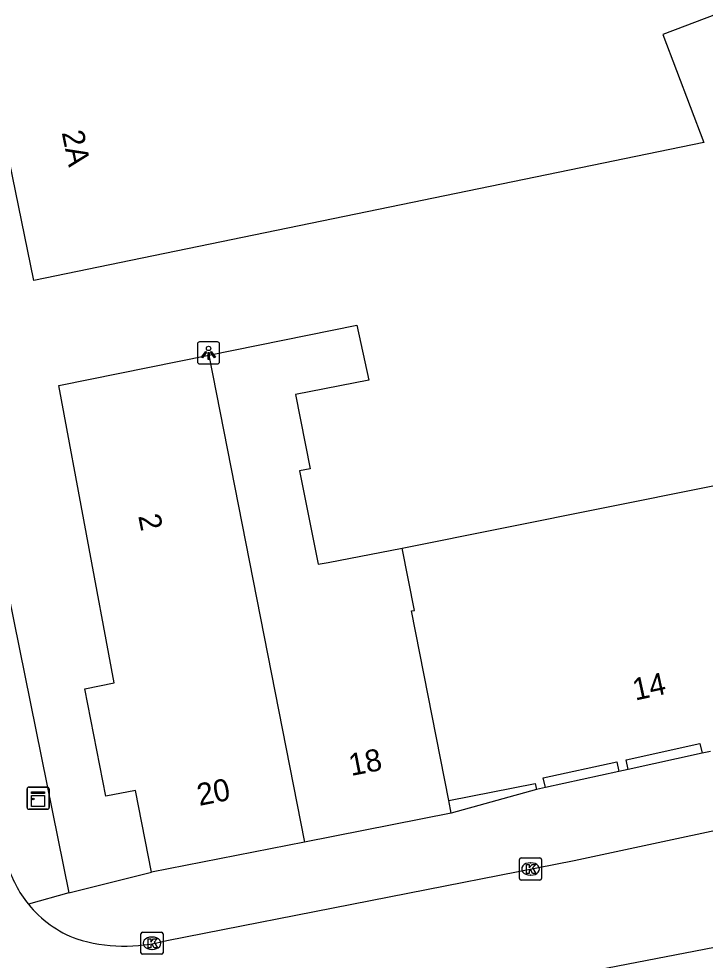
# Model space of a CAD drawing. Extents: x 160026 to 161302, y 384757 to 385701.
# Drawn here: x 160735.46 to 160766.52, y 384838.71 to 384881.28 of the extents above; entities that cross this region are included whole.
import ezdxf

# ---------------------------------------------------------------- set-up
doc = ezdxf.new("R2010")
doc.units = 0
for name, color, linetype in [('IMGEO_Kast', 7, 'Continuous'), ('IMGEO_Kolk', 7, 'Continuous'), ('IMGEO_Lichtpunt', 7, 'Continuous'), ('IMGEO_Pand', 7, 'Continuous'), ('IMGEO_Pand_nummerreeks', 7, 'Continuous'), ('IMGEO_Rijbaan_lokaal_open', 7, 'Continuous'), ('IMGEO_Voetpad_open', 7, 'Continuous')]:
    doc.layers.add(name, color=color, linetype=linetype)

msp = doc.modelspace()

# ---------------------------------------------------------------- linework, layer by layer
at = {"layer": 'IMGEO_Kast'}
for p, q in [((160735.835, 384845.616), (160735.835, 384846.457)), ((160735.835, 384846.457), (160735.835, 384845.616)), ((160735.91, 384846.541), (160736.751, 384846.541)), ((160736.751, 384846.541), (160735.91, 384846.541)), ((160736.835, 384846.466), (160736.835, 384845.625)), ((160736.835, 384845.625), (160736.835, 384846.466)), ((160736.76, 384845.541), (160735.919, 384845.541)), ((160735.919, 384845.541), (160736.76, 384845.541))]:
    msp.add_line(p, q, dxfattribs=at)
for points in [[(160736.03, 384846.331), (160736.63, 384846.331), (160736.63, 384846.246), (160736.03, 384846.246), (160736.03, 384846.331)], [(160736.03, 384846.156), (160736.63, 384846.156), (160736.63, 384845.667), (160736.03, 384845.667), (160736.03, 384846.156)]]:
    msp.add_lwpolyline(points, dxfattribs=at)
msp.add_circle((160736.114, 384846.005), 0.0377, dxfattribs=at)
for centre, start, end in [((160735.913, 384846.463), 92.4484, 184.2845), ((160735.913, 384846.463), 92.4484, 184.2845), ((160736.757, 384846.463), 2.4484, 94.2845), ((160736.757, 384846.463), 2.4484, 94.2845), ((160735.913, 384845.619), 182.4484, 274.2845), ((160735.913, 384845.619), 182.4484, 274.2845), ((160736.757, 384845.619), 272.4484, 4.2845), ((160736.757, 384845.619), 272.4484, 4.2845)]:
    msp.add_arc(centre, 0.0779, start, end, dxfattribs=at)
at = {"layer": 'IMGEO_Kolk'}
for p, q in [((160758.194, 384843.338), (160759.046, 384843.338)), ((160758.119, 384842.412), (160758.119, 384843.264)), ((160758.607, 384843.118), (160758.632, 384843.118)), ((160759.12, 384843.264), (160759.12, 384842.412)), ((160758.63, 384842.558), (160758.605, 384842.558)), ((160759.046, 384842.338), (160758.194, 384842.338)), ((160741.063, 384839.98), (160741.915, 384839.98)), ((160740.988, 384839.054), (160740.988, 384839.906)), ((160741.476, 384839.76), (160741.501, 384839.76)), ((160741.989, 384839.906), (160741.989, 384839.054)), ((160741.499, 384839.2), (160741.474, 384839.2)), ((160741.915, 384838.98), (160741.063, 384838.98))]:
    msp.add_line(p, q, dxfattribs=at)
for points in [[(160758.194, 384843.338), (160759.046, 384843.338)], [(160758.119, 384842.412), (160758.119, 384843.264)], [(160758.44, 384843.038), (160758.563, 384843.038), (160758.563, 384842.887), (160758.693, 384843.038), (160758.857, 384843.038), (160758.711, 384842.887), (160758.864, 384842.638), (160758.712, 384842.638), (160758.627, 384842.802), (160758.563, 384842.735), (160758.563, 384842.638), (160758.44, 384842.638), (160758.44, 384843.038)], [(160759.12, 384843.264), (160759.12, 384842.412)], [(160759.046, 384842.338), (160758.194, 384842.338)], [(160741.063, 384839.98), (160741.915, 384839.98)], [(160740.988, 384839.054), (160740.988, 384839.906)], [(160741.309, 384839.68), (160741.432, 384839.68), (160741.432, 384839.529), (160741.562, 384839.68), (160741.726, 384839.68), (160741.58, 384839.529), (160741.733, 384839.28), (160741.581, 384839.28), (160741.496, 384839.444), (160741.432, 384839.377), (160741.432, 384839.28), (160741.309, 384839.28), (160741.309, 384839.68)], [(160741.989, 384839.906), (160741.989, 384839.054)], [(160741.915, 384838.98), (160741.063, 384838.98)]]:
    msp.add_lwpolyline(points, dxfattribs=at)
for centre, start, end in [((160758.196, 384843.262), 91.552, 178.448), ((160758.196, 384843.262), 91.552, 178.448), ((160759.044, 384843.262), 1.552, 88.448), ((160759.044, 384843.262), 1.552, 88.448), ((160758.196, 384842.414), 181.552, 268.448), ((160758.196, 384842.414), 181.552, 268.448), ((160759.044, 384842.414), 271.552, 358.448), ((160759.044, 384842.414), 271.552, 358.448), ((160741.065, 384839.904), 91.552, 178.448), ((160741.065, 384839.904), 91.552, 178.448), ((160741.913, 384839.904), 1.552, 88.448), ((160741.913, 384839.904), 1.552, 88.448), ((160741.065, 384839.056), 181.552, 268.448), ((160741.065, 384839.056), 181.552, 268.448), ((160741.913, 384839.056), 271.552, 358.448), ((160741.913, 384839.056), 271.552, 358.448)]:
    msp.add_arc(centre, 0.0765, start, end, dxfattribs=at)
for centre, major_axis, ratio, start_param, end_param in [((160758.606, 384842.838), (-0.387, 0.002), 0.722429, 4.712389, 7.853982), ((160758.631, 384842.838), (-0.39, 0.002), 0.717154, 1.570796, 4.712389), ((160741.475, 384839.48), (-0.387, 0.002), 0.722429, 4.712389, 7.853982), ((160741.5, 384839.48), (-0.39, 0.002), 0.717154, 1.570796, 4.712389)]:
    msp.add_ellipse(centre, major_axis=major_axis, ratio=ratio, start_param=start_param, end_param=end_param, dxfattribs=at)
at = {"layer": 'IMGEO_Lichtpunt'}
for p, q in [((160743.548, 384866.578), (160743.548, 384865.771)), ((160743.548, 384866.578), (160743.548, 384865.771)), ((160744.45, 384866.673), (160743.642, 384866.673)), ((160744.45, 384866.673), (160743.642, 384866.673)), ((160744.544, 384865.771), (160744.544, 384866.578)), ((160744.544, 384865.771), (160744.544, 384866.578)), ((160743.642, 384865.677), (160744.45, 384865.677)), ((160743.642, 384865.677), (160744.45, 384865.677))]:
    msp.add_line(p, q, dxfattribs=at)
for points in [[(160743.922, 384866.242), (160743.961, 384866.214), (160743.773, 384865.952), (160743.735, 384865.979), (160743.922, 384866.242)], [(160744.024, 384866.194), (160744.071, 384866.194), (160744.071, 384865.872), (160744.024, 384865.872), (160744.024, 384866.194)], [(160744.134, 384866.214), (160744.172, 384866.241), (160744.359, 384865.979), (160744.32, 384865.951), (160744.134, 384866.214)]]:
    msp.add_lwpolyline(points, dxfattribs=at)
msp.add_circle((160744.047, 384866.376), 0.0994, dxfattribs=at)
for centre, start, end in [((160743.642, 384866.578), 90, 180), ((160743.642, 384866.578), 90, 180), ((160744.45, 384866.578), 0, 90), ((160744.45, 384866.578), 0, 90), ((160743.642, 384865.771), 180, 270), ((160743.642, 384865.771), 180, 270), ((160744.45, 384865.771), 270, 0), ((160744.45, 384865.771), 270, 360)]:
    msp.add_arc(centre, 0.0946, start, end, dxfattribs=at)
at = {"layer": 'IMGEO_Pand'}
for points in [[(160788.586, 384888.745), (160779.859, 384885.441), (160779.549, 384886.257), (160771.521, 384883.201), (160771.642, 384882.873), (160771.014, 384882.635), (160770.893, 384882.963), (160764.6, 384880.569), (160766.456, 384875.692), (160741.042, 384870.459), (160736.144, 384869.451), (160733.533, 384882.133), (160738.872, 384883.188), (160742.841, 384883.972), (160743.29, 384881.699), (160757.729, 384884.553), (160757.227, 384887.095), (160762.126, 384888.063), (160755.507, 384907.922), (160782.595, 384922.812)], [(160744.058, 384866.069), (160750.751, 384867.422), (160751.295, 384864.939), (160747.98, 384864.287), (160748.643, 384860.93), (160748.171, 384860.836), (160749.007, 384856.619), (160749.461, 384856.696), (160752.81, 384857.345)], [(160741.463, 384842.694), (160740.735, 384846.394), (160739.402, 384846.132), (160738.448, 384850.99), (160739.78, 384851.251), (160737.271, 384864.696), (160744.058, 384866.069)], [(160744.058, 384866.069), (160748.384, 384844.055)], [(160752.81, 384857.345), (160771.222, 384861.039)], [(160754.915, 384845.94), (160753.229, 384854.506), (160753.366, 384854.533), (160752.81, 384857.345)], [(160763.04, 384847.339), (160762.943, 384847.779), (160766.284, 384848.51), (160766.381, 384848.07)], [(160766.762, 384848.153), (160766.381, 384848.07)], [(160759.289, 384846.519), (160759.192, 384846.959), (160762.523, 384847.687), (160762.62, 384847.247)], [(160763.04, 384847.339), (160762.62, 384847.247)], [(160754.915, 384845.94), (160758.827, 384846.709), (160758.888, 384846.431)], [(160759.289, 384846.519), (160758.888, 384846.431)], [(160755.026, 384845.361), (160754.915, 384845.94)], [(160755.026, 384845.361), (160748.384, 384844.055)], [(160748.384, 384844.055), (160741.463, 384842.694)]]:
    msp.add_lwpolyline(points, dxfattribs=at)
at = {"layer": 'IMGEO_Rijbaan_lokaal_open'}
for points in [[(160742.153, 384839.609), (160760.591, 384843.223), (160771.222, 384845.501), (160780.663, 384847.643), (160789.637, 384849.89), (160797.435, 384852.004)], [(160664.308, 384819.309), (160685.493, 384823.418), (160705.679, 384827.354), (160724.853, 384831.104), (160742.683, 384834.606), (160759.916, 384837.951), (160776.155, 384841.085)]]:
    msp.add_lwpolyline(points, dxfattribs=at)
for centre, radius, start, end in [((160739.907, 384844.507), 5.17, 195.9301, 219.0776), ((160739.891, 384844.491), 5.147, 219.054, 249.4009), ((160740.227, 384846.693), 7.341, 252.992, 285.2076)]:
    msp.add_arc(centre, radius, start, end, dxfattribs=at)
at = {"layer": 'IMGEO_Voetpad_open'}
for points in [[(160736.412, 384977.212), (160728.453, 384913.716), (160726.598, 384898.918), (160727.272, 384893.08), (160729.664, 384881.344), (160732.249, 384868.657), (160733.225, 384863.871), (160737.731, 384841.761)], [(160766.381, 384848.07), (160763.04, 384847.339)], [(160762.62, 384847.247), (160759.289, 384846.519)], [(160758.888, 384846.431), (160755.026, 384845.361)], [(160737.731, 384841.761), (160741.463, 384842.694)], [(160737.731, 384841.761), (160735.894, 384841.248)]]:
    msp.add_lwpolyline(points, dxfattribs=at)

# ---------------------------------------------------------------- texts
at = {"layer": 'IMGEO_Pand_nummerreeks'}
for s, rotation, p in [('2A', 281.6308, (160737.399, 384876.143)), ('2', 281.1265, (160740.863, 384858.803)), ('14', 12.3416, (160763.357, 384850.449)), ('18', 11.1268, (160750.5, 384847.04)), ('20', 11.1251, (160743.632, 384845.689))]:
    msp.add_text(s, height=1, rotation=rotation, dxfattribs=at).set_placement(p)

doc.saveas('drawing.dxf')
